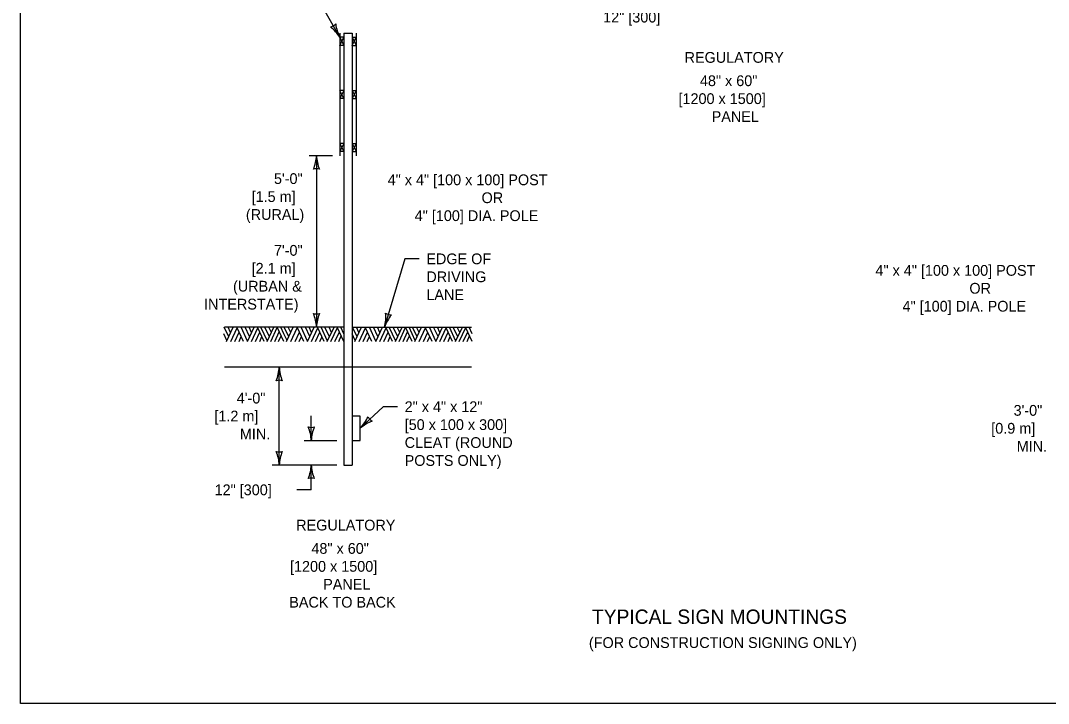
# Model space of a CAD drawing. Extents: x 49991.4 to 50021, y 49987.6 to 50011.4.
# Drawn here: x 49999.38 to 50005.11, y 49987.8 to 49991.61 of the extents above; entities that cross this region are included whole.
import ezdxf

# ---------------------------------------------------------------- set-up
doc = ezdxf.new("R2010")
doc.units = 0
for name, color, linetype in [('Level 1', 7, 'Continuous'), ('Level 2', 7, 'Continuous'), ('Level 3', 7, 'Continuous'), ('Level 4', 7, 'Continuous')]:
    doc.layers.add(name, color=color, linetype=linetype)

msp = doc.modelspace()

# ---------------------------------------------------------------- linework, layer by layer
at = {"layer": 'Level 1'}
for p, q in [((50001.1627, 49991.5366), (50001.1627, 49990.8539)), ((50001.1856, 49991.514), (50001.1627, 49991.514)), ((50001.1627, 49991.514), (50001.1856, 49991.4683)), ((50001.1627, 49991.4683), (50001.1856, 49991.514)), ((50001.1856, 49991.5366), (50001.1856, 49989.6749)), ((50001.1856, 49991.5366), (50001.231, 49991.5366)), ((50001.231, 49991.5366), (50001.231, 49989.6749)), ((50001.231, 49991.514), (50001.2539, 49991.514)), ((50001.231, 49991.514), (50001.2539, 49991.4683)), ((50001.231, 49991.4683), (50001.2539, 49991.514)), ((50001.2539, 49991.5366), (50001.2539, 49990.8539)), ((50001.1856, 49991.4683), (50001.1627, 49991.4683)), ((50001.231, 49991.4683), (50001.2539, 49991.4683)), ((50001.1856, 49991.2181), (50001.1627, 49991.2181)), ((50001.1856, 49991.2181), (50001.1627, 49991.1725)), ((50001.1856, 49991.1725), (50001.1627, 49991.2181)), ((50001.231, 49991.2181), (50001.2539, 49991.2181)), ((50001.231, 49991.2181), (50001.2539, 49991.1725)), ((50001.2539, 49991.2181), (50001.231, 49991.1725)), ((50001.1856, 49991.1725), (50001.1627, 49991.1725)), ((50001.231, 49991.1725), (50001.2539, 49991.1725)), ((50001.1856, 49990.9221), (50001.1627, 49990.9221)), ((50001.1627, 49990.9221), (50001.1856, 49990.8766)), ((50001.1856, 49990.9221), (50001.1627, 49990.8766)), ((50001.231, 49990.9221), (50001.2539, 49990.9221)), ((50001.2539, 49990.9221), (50001.231, 49990.8766)), ((50001.231, 49990.9221), (50001.2539, 49990.8766)), ((50001.1856, 49990.8766), (50001.1627, 49990.8766)), ((50001.231, 49990.8766), (50001.2539, 49990.8766)), ((50000.5436, 49989.8439), (50000.5183, 49989.8979)), ((50001.1856, 49989.8979), (50000.5193, 49989.8979)), ((50000.5312, 49989.8175), (50000.5685, 49989.8979)), ((50000.5544, 49989.8672), (50000.5403, 49989.8979)), ((50000.5553, 49989.8175), (50000.591, 49989.8942)), ((50000.6268, 49989.8175), (50000.5893, 49989.8979)), ((50000.6488, 49989.8198), (50000.6124, 49989.8979)), ((50000.6602, 49989.8447), (50000.6358, 49989.8979)), ((50000.6477, 49989.8175), (50000.6849, 49989.8979)), ((50000.6707, 49989.8682), (50000.6572, 49989.8979)), ((50000.6699, 49989.8175), (50000.7055, 49989.894)), ((50000.7414, 49989.8175), (50000.7036, 49989.8979)), ((50000.7596, 49989.82), (50000.7233, 49989.8979)), ((50000.7703, 49989.8432), (50000.745, 49989.8979)), ((50000.7583, 49989.8175), (50000.7955, 49989.8981)), ((50000.7816, 49989.8674), (50000.7676, 49989.8979)), ((50000.7783, 49989.8175), (50000.8143, 49989.8953)), ((50000.8507, 49989.8175), (50000.8135, 49989.8979)), ((50000.8507, 49989.8604), (50000.8335, 49989.8979)), ((50000.8783, 49989.8439), (50000.8531, 49989.8979)), ((50000.8661, 49989.8175), (50000.9034, 49989.8979)), ((50000.8892, 49989.8672), (50000.8752, 49989.8979)), ((50000.8902, 49989.8175), (50000.9259, 49989.8942)), ((50000.9616, 49989.8175), (50000.9242, 49989.8979)), ((50000.9835, 49989.8198), (50000.9473, 49989.8979)), ((50000.995, 49989.8447), (50000.9706, 49989.8979)), ((50000.9826, 49989.8175), (50001.0198, 49989.8979)), ((50001.0055, 49989.8682), (50000.9919, 49989.8979)), ((50001.0048, 49989.8175), (50001.0402, 49989.894)), ((50001.0762, 49989.8175), (50001.0385, 49989.8979)), ((50001.0945, 49989.82), (50001.0582, 49989.8979)), ((50001.1052, 49989.8432), (50001.0799, 49989.8979)), ((50001.0931, 49989.8175), (50001.1304, 49989.8981)), ((50001.1165, 49989.8674), (50001.1025, 49989.8979)), ((50001.1132, 49989.8175), (50001.1491, 49989.8953)), ((50001.1856, 49989.8175), (50001.1483, 49989.8979)), ((50001.1856, 49989.8604), (50001.1684, 49989.8979)), ((50001.231, 49989.8979), (50001.8973, 49989.8979)), ((50001.2586, 49989.8439), (50001.2334, 49989.8979)), ((50001.2464, 49989.8175), (50001.2837, 49989.8979)), ((50001.2694, 49989.8672), (50001.2555, 49989.8979)), ((50001.2705, 49989.8175), (50001.3062, 49989.8942)), ((50001.3419, 49989.8175), (50001.3044, 49989.8979)), ((50001.3638, 49989.8198), (50001.3276, 49989.8979)), ((50001.3754, 49989.8447), (50001.3509, 49989.8979)), ((50001.3629, 49989.8175), (50001.4001, 49989.8979)), ((50001.3858, 49989.8682), (50001.3722, 49989.8979)), ((50001.3851, 49989.8175), (50001.4205, 49989.894)), ((50001.4565, 49989.8175), (50001.4188, 49989.8979)), ((50001.4748, 49989.82), (50001.4385, 49989.8979)), ((50001.4855, 49989.8432), (50001.4602, 49989.8979)), ((50001.4734, 49989.8175), (50001.5107, 49989.8981)), ((50001.4967, 49989.8674), (50001.4828, 49989.8979)), ((50001.4935, 49989.8175), (50001.5293, 49989.8953)), ((50001.5659, 49989.8175), (50001.5286, 49989.8979)), ((50001.5659, 49989.8604), (50001.5487, 49989.8979)), ((50001.5935, 49989.8439), (50001.5683, 49989.8979)), ((50001.5813, 49989.8175), (50001.6186, 49989.8979)), ((50001.6043, 49989.8672), (50001.5904, 49989.8979)), ((50001.6054, 49989.8175), (50001.641, 49989.8942)), ((50001.6768, 49989.8175), (50001.6393, 49989.8979)), ((50001.6987, 49989.8198), (50001.6625, 49989.8979)), ((50001.7102, 49989.8447), (50001.6857, 49989.8979)), ((50001.6977, 49989.8175), (50001.7348, 49989.8979)), ((50001.7207, 49989.8682), (50001.7071, 49989.8979)), ((50001.7199, 49989.8175), (50001.7554, 49989.894)), ((50001.7914, 49989.8175), (50001.7537, 49989.8979)), ((50001.8096, 49989.82), (50001.7734, 49989.8979)), ((50001.8203, 49989.8432), (50001.7951, 49989.8979)), ((50001.8083, 49989.8175), (50001.8456, 49989.8981)), ((50001.8316, 49989.8674), (50001.8176, 49989.8979)), ((50001.8283, 49989.8175), (50001.8642, 49989.8953)), ((50001.9008, 49989.8175), (50001.8635, 49989.8979)), ((50001.9008, 49989.8604), (50001.8834, 49989.8979)), ((50000.5336, 49989.8225), (50000.5158, 49989.8604)), ((50000.5783, 49989.8175), (50000.6026, 49989.8697)), ((50000.6009, 49989.8175), (50000.6138, 49989.8452)), ((50000.6928, 49989.8175), (50000.7169, 49989.8697)), ((50000.7164, 49989.8175), (50000.7286, 49989.8445)), ((50000.8002, 49989.8175), (50000.8253, 49989.8722)), ((50000.8215, 49989.8175), (50000.836, 49989.8491)), ((50000.8684, 49989.8225), (50000.8507, 49989.8604)), ((50000.9132, 49989.8175), (50000.9373, 49989.8697)), ((50000.9358, 49989.8175), (50000.9486, 49989.8452)), ((50001.0277, 49989.8175), (50001.0517, 49989.8697)), ((50001.0512, 49989.8175), (50001.0635, 49989.8445)), ((50001.1351, 49989.8175), (50001.1602, 49989.8722)), ((50001.1564, 49989.8175), (50001.1709, 49989.8491)), ((50001.2487, 49989.8225), (50001.231, 49989.8604)), ((50001.2934, 49989.8175), (50001.3176, 49989.8697)), ((50001.3161, 49989.8175), (50001.3289, 49989.8452)), ((50001.408, 49989.8175), (50001.432, 49989.8697)), ((50001.4315, 49989.8175), (50001.4438, 49989.8445)), ((50001.5154, 49989.8175), (50001.5404, 49989.8722)), ((50001.5367, 49989.8175), (50001.5512, 49989.8491)), ((50001.5836, 49989.8225), (50001.5659, 49989.8604)), ((50001.6282, 49989.8175), (50001.6525, 49989.8697)), ((50001.651, 49989.8175), (50001.6638, 49989.8452)), ((50001.7429, 49989.8175), (50001.7669, 49989.8697)), ((50001.7664, 49989.8175), (50001.7785, 49989.8445)), ((50001.8503, 49989.8175), (50001.8753, 49989.8722)), ((50001.8716, 49989.8175), (50001.886, 49989.8491)), ((50001.8973, 49989.6749), (50000.5193, 49989.6749))]:
    msp.add_line(p, q, dxfattribs=at)
msp.add_lwpolyline([(49999.3835, 49998.9992), (50016.7501, 49998.9992), (50016.7501, 49987.7988), (49999.3835, 49987.7988)], close=True, dxfattribs=at)
at = {"layer": 'Level 3'}
for p, q in [((50001.1627, 49991.514), (50000.9929, 49991.8132)), ((50001.1227, 49990.8539), (50000.9926, 49990.8539)), ((50001.0326, 49990.8539), (50001.0326, 49989.8979)), ((50001.525, 49990.2785), (50001.4124, 49989.8979)), ((50001.605, 49990.2785), (50001.525, 49990.2785)), ((50000.8252, 49989.1287), (50000.8252, 49989.6749)), ((50001.4042, 49989.4539), (50001.2765, 49989.3335)), ((50001.4842, 49989.4539), (50001.4042, 49989.4539)), ((50001.0038, 49989.2652), (50001.0038, 49989.4038)), ((50000.9638, 49989.2652), (50001.1456, 49989.2652)), ((50001.1456, 49989.1287), (50000.7852, 49989.1287)), ((50001.0038, 49988.9902), (50001.0038, 49989.1287)), ((50001.0038, 49988.9902), (50000.9238, 49988.9902))]:
    msp.add_line(p, q, dxfattribs=at)
for centre, radius, start, end in [((50001.0992, 49991.6254), 0.0548, 281.8338, 317.5562), ((50000.9662, 49991.3887), 0.233, 32.5223, 51.7721), ((50001.3602, 49991.6161), 0.2223, 187.151, 207.3345), ((50000.8105, 49990.8631), 0.2223, 337.456, 357.6395), ((50001.2653, 49990.8654), 0.233, 182.8273, 202.0772), ((50001.0326, 49990.7257), 0.0548, 72.1388, 107.8612), ((50001.0326, 49990.0261), 0.0548, 252.1388, 287.8612), ((50000.7999, 49989.8864), 0.233, 2.8273, 22.0772), ((50001.2547, 49989.8887), 0.2223, 157.456, 177.6395), ((50001.186, 49989.9529), 0.233, 346.3465, 5.5964), ((50001.6228, 49989.8261), 0.2223, 140.9752, 161.1587), ((50001.4488, 49990.0208), 0.0548, 235.658, 271.3804), ((50000.5925, 49989.6864), 0.233, 337.9228, 357.1727), ((50001.0473, 49989.6841), 0.2223, 182.3605, 202.544), ((50000.8252, 49989.5467), 0.0548, 72.1388, 107.8612), ((50001.1174, 49989.4888), 0.2223, 315.6989, 335.8824), ((50001.4279, 49989.1564), 0.233, 111.2612, 130.5111), ((50001.3698, 49989.4215), 0.0548, 205.4772, 241.1996), ((50000.7817, 49989.256), 0.2223, 2.3605, 22.544), ((50001.0038, 49989.3934), 0.0548, 252.1388, 287.8612), ((50001.2365, 49989.2537), 0.233, 157.9228, 177.1727), ((50000.6031, 49989.1195), 0.2223, 2.3605, 22.544), ((50000.8252, 49989.2569), 0.0548, 252.1388, 287.8612), ((50001.0579, 49989.1172), 0.233, 157.9228, 177.1727), ((50000.7711, 49989.1402), 0.233, 337.9228, 357.1727), ((50001.2259, 49989.1378), 0.2223, 182.3605, 202.544), ((50001.0038, 49989.0005), 0.0548, 72.1388, 107.8612)]:
    msp.add_arc(centre, radius, start, end, dxfattribs=at)
at = {"layer": 'Level 4'}
for p, q in [((50001.1856, 49989.6749), (50001.1856, 49989.1286)), ((50001.231, 49989.6749), (50001.231, 49989.1286)), ((50001.2765, 49989.4017), (50001.2311, 49989.4017)), ((50001.2765, 49989.2652), (50001.2765, 49989.4017)), ((50001.2311, 49989.2652), (50001.2765, 49989.2652)), ((50001.1856, 49989.1286), (50001.231, 49989.1286))]:
    msp.add_line(p, q, dxfattribs=at)

# ---------------------------------------------------------------- texts
at = {"layer": 'Level 2'}
for s, height, p in [('12" [300]', 0.06, (50002.6303, 49991.5967)), ('REGULATORY', 0.06, (50003.0842, 49991.3719)), ('48" x 60"', 0.06, (50003.1697, 49991.2419)), ('[1200 x 1500]', 0.06, (50003.0503, 49991.1419)), ('PANEL', 0.06, (50003.2351, 49991.0419)), ('5\'-0"', 0.06, (50000.7957, 49990.6959)), ('4" x 4" [100 x 100] POST', 0.06, (50001.4295, 49990.6893)), ('[1.5 m]', 0.06, (50000.6712, 49990.5959)), ('OR', 0.06, (50001.9528, 49990.5893)), (' (RURAL)', 0.06, (50000.6169, 49990.4959)), ('4" [100] DIA. POLE', 0.06, (50001.5802, 49990.4893)), ('7\'-0"', 0.06, (50000.7957, 49990.2959)), ('EDGE OF', 0.06, (50001.645, 49990.2485)), ('[2.1 m]', 0.06, (50000.6712, 49990.1959)), ('4" x 4" [100 x 100] POST', 0.06, (50004.1481, 49990.1842)), ('DRIVING', 0.06, (50001.645, 49990.1485)), ('(URBAN &', 0.06, (50000.5676, 49990.0959)), ('OR', 0.06, (50004.6714, 49990.0842)), ('LANE', 0.06, (50001.645, 49990.0485)), ('INTERSTATE)', 0.06, (50000.4065, 49989.9959)), ('4" [100] DIA. POLE', 0.06, (50004.2988, 49989.9842)), ('4\'-0"', 0.06, (50000.5883, 49989.4718)), ('[1.2 m]', 0.06, (50000.4638, 49989.3718)), ('2" x 4" x 12" ', 0.06, (50001.5242, 49989.4239)), ('3\'-0"', 0.06, (50004.9177, 49989.4034)), ('[50 x 100 x 300]', 0.06, (50001.5242, 49989.3239)), ('MIN.', 0.06, (50000.6056, 49989.2718)), ('[0.9 m]', 0.06, (50004.7932, 49989.3034)), ('CLEAT (ROUND', 0.06, (50001.5242, 49989.2239)), ('MIN.', 0.06, (50004.935, 49989.2034)), ('POSTS ONLY)', 0.06, (50001.5242, 49989.1239)), ('12" [300]', 0.06, (50000.465, 49988.9602)), ('REGULATORY', 0.06, (50000.9196, 49988.7634)), ('48" x 60"', 0.06, (50001.0045, 49988.6334)), ('[1200 x 1500]', 0.06, (50000.8851, 49988.5334)), ('PANEL', 0.06, (50001.07, 49988.4334)), ('BACK TO BACK', 0.06, (50000.8811, 49988.3334)), ('TYPICAL SIGN MOUNTINGS', 0.08, (50002.5684, 49988.2426)), ('(FOR CONSTRUCTION SIGNING ONLY)', 0.06, (50002.5509, 49988.1082))]:
    msp.add_text(s, height=height, dxfattribs=at).set_placement(p)

doc.saveas('drawing.dxf')
